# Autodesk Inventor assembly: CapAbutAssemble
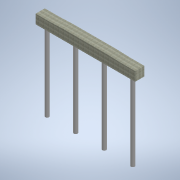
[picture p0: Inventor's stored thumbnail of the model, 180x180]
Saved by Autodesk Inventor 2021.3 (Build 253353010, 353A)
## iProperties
Created: 2021-11
Part Number: CapAbutAssemble
Document SubType Name: Assembly
Designer: u1426
Author: u1426
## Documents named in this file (3)
- S:\Bridge_CADD\Other\SampleBridgeInventor\CapAbutAssemble.iam
- S:\Bridge_CADD\Other\SampleBridgeInventor\CapAbut.ipt
- S:\Bridge_CADD\Other\SampleBridgeInventor\Pile16.ipt
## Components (5 placed, 2 different names)
1. CapAbut:1 — Mate:1, Mate:2, Flush:1, Mate:3
2. Pile16:1 — Mate:2, Flush:1, Mate:3
3. Pile16:2
4. Pile16:3
5. Pile16:4
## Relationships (4: Mate 3, Flush 1)
- Mate:1: CapAbut:1
- Mate:2: CapAbut:1 ↔ Pile16:1
- Flush:1: CapAbut:1 ↔ Pile16:1
- Mate:3: CapAbut:1 ↔ Pile16:1
